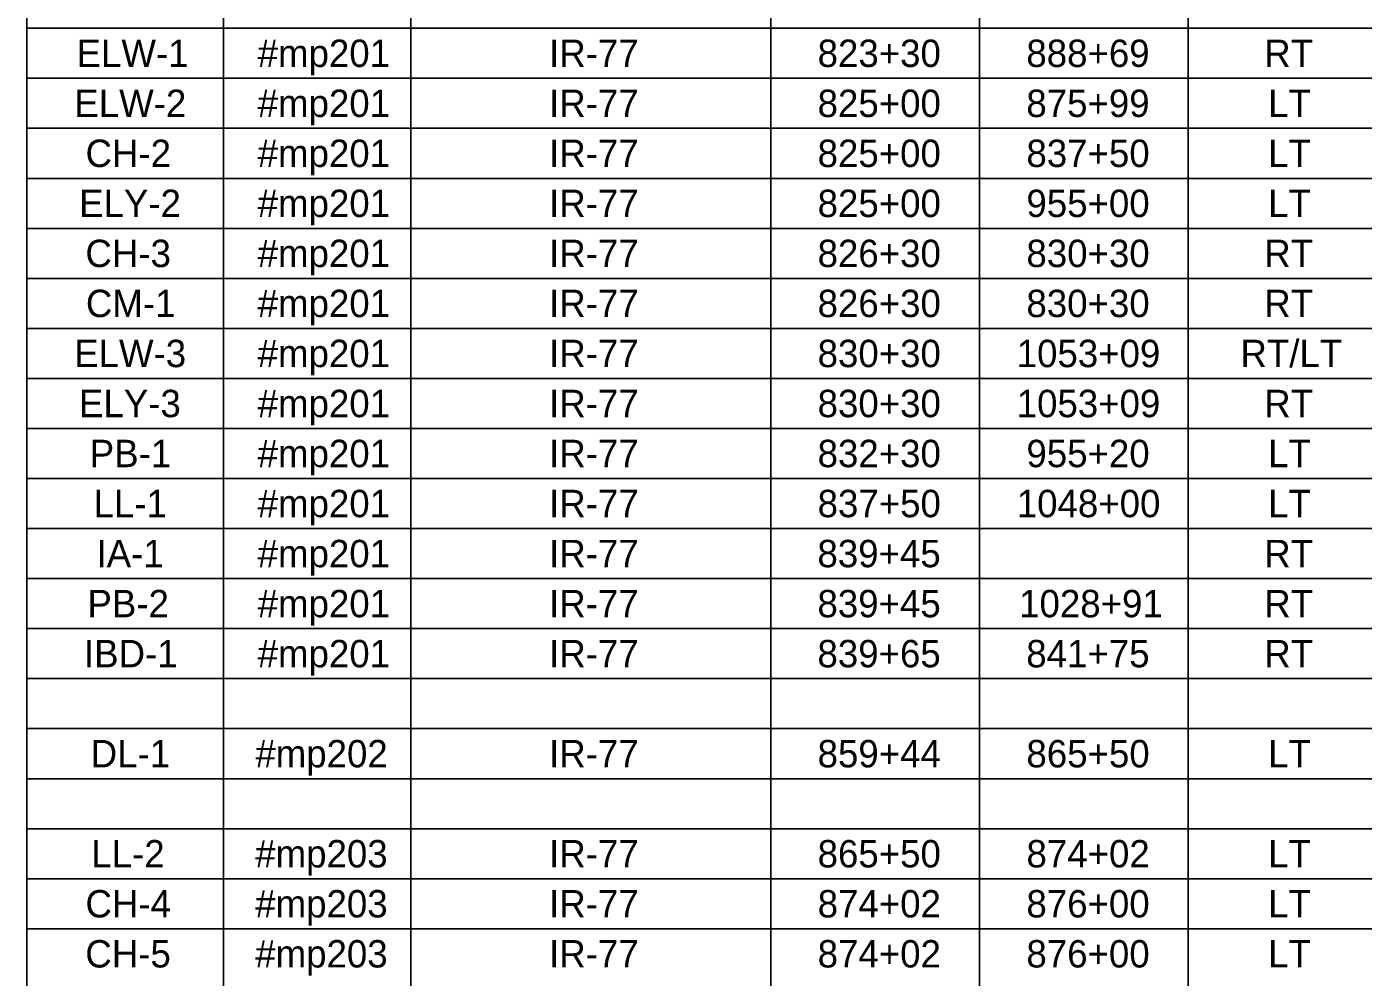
# Model space of a CAD drawing. Extents: x 91011267 to 91022583, y 37007614 to 37014266.
# Drawn here: x 91011277.4 to 91011644.4, y 37009419.7 to 37009680.8 of the extents above; entities that cross this region are included whole.
import ezdxf

# ---------------------------------------------------------------- set-up
doc = ezdxf.new("R2010")
doc.units = 0
doc.layers.add('SC_Scratch2', color=7, linetype='Continuous')
doc.layers.add('SH_Data', color=7, linetype='Continuous')

msp = doc.modelspace()

# ---------------------------------------------------------------- linework, layer by layer
at = {"layer": 'SC_Scratch2'}
msp.add_lwpolyline([(91011277.35, 37009944.63), (91012802.35, 37009944.63), (91012802.35, 37008894.63), (91011277.35, 37008894.63)], close=True, dxfattribs=at)
at = {"layer": 'SH_Data'}
for p, q in [((91011277.35, 37009762.76), (91011277.35, 37009652.86)), ((91011331.39, 37009762.76), (91011331.39, 37009652.86)), ((91011382.8, 37009762.76), (91011382.8, 37009652.86)), ((91011481.65, 37009762.76), (91011481.65, 37009652.86)), ((91011538.99, 37009762.76), (91011538.99, 37009652.86)), ((91011596.32, 37009762.76), (91011596.32, 37009652.86)), ((91011277.35, 37009680.33), (91011596.32, 37009680.33)), ((91011596.32, 37009680.33), (91011650.36, 37009680.33)), ((91011277.35, 37009666.59), (91011596.32, 37009666.59)), ((91011596.32, 37009666.59), (91011650.36, 37009666.59)), ((91011277.35, 37009652.86), (91011596.32, 37009652.86)), ((91011277.35, 37009652.86), (91011277.35, 37009639.12)), ((91011331.39, 37009652.86), (91011331.39, 37009639.12)), ((91011382.8, 37009652.86), (91011382.8, 37009639.12)), ((91011481.65, 37009652.86), (91011481.65, 37009639.12)), ((91011538.99, 37009652.86), (91011538.99, 37009639.12)), ((91011596.32, 37009652.86), (91011650.36, 37009652.86)), ((91011596.32, 37009652.86), (91011596.32, 37009639.12)), ((91011277.35, 37009639.12), (91011596.32, 37009639.12)), ((91011277.35, 37009639.12), (91011277.35, 37009611.64)), ((91011331.39, 37009639.12), (91011331.39, 37009611.64)), ((91011382.8, 37009639.12), (91011382.8, 37009611.64)), ((91011481.65, 37009639.12), (91011481.65, 37009611.64)), ((91011538.99, 37009639.12), (91011538.99, 37009611.64)), ((91011596.32, 37009639.12), (91011650.36, 37009639.12)), ((91011596.32, 37009639.12), (91011596.32, 37009611.64)), ((91011277.35, 37009625.38), (91011596.32, 37009625.38)), ((91011596.32, 37009625.38), (91011650.36, 37009625.38)), ((91011277.35, 37009611.64), (91011596.32, 37009611.64)), ((91011277.35, 37009611.64), (91011277.35, 37009597.9)), ((91011331.39, 37009611.64), (91011331.39, 37009597.9)), ((91011382.8, 37009611.64), (91011382.8, 37009597.9)), ((91011481.65, 37009611.64), (91011481.65, 37009597.9)), ((91011538.99, 37009611.64), (91011538.99, 37009597.9)), ((91011596.32, 37009611.64), (91011650.36, 37009611.64)), ((91011596.32, 37009611.64), (91011596.32, 37009597.9)), ((91011277.35, 37009597.9), (91011596.32, 37009597.9)), ((91011277.35, 37009597.9), (91011277.35, 37009584.17)), ((91011331.39, 37009597.9), (91011331.39, 37009584.17)), ((91011382.8, 37009597.9), (91011382.8, 37009584.17)), ((91011481.65, 37009597.9), (91011481.65, 37009584.17)), ((91011538.99, 37009597.9), (91011538.99, 37009584.17)), ((91011596.32, 37009597.9), (91011650.36, 37009597.9)), ((91011596.32, 37009597.9), (91011596.32, 37009584.17)), ((91011277.35, 37009584.17), (91011596.32, 37009584.17)), ((91011277.35, 37009584.17), (91011277.35, 37009570.43)), ((91011331.39, 37009584.17), (91011331.39, 37009570.43)), ((91011382.8, 37009584.17), (91011382.8, 37009570.43)), ((91011481.65, 37009584.17), (91011481.65, 37009570.43)), ((91011538.99, 37009584.17), (91011538.99, 37009570.43)), ((91011596.32, 37009584.17), (91011650.36, 37009584.17)), ((91011596.32, 37009584.17), (91011596.32, 37009570.43)), ((91011277.35, 37009570.43), (91011596.32, 37009570.43)), ((91011277.35, 37009570.43), (91011277.35, 37009364.35)), ((91011331.39, 37009570.43), (91011331.39, 37009364.35)), ((91011382.8, 37009570.43), (91011382.8, 37009364.35)), ((91011481.65, 37009570.43), (91011481.65, 37009364.35)), ((91011538.99, 37009570.43), (91011538.99, 37009364.35)), ((91011596.32, 37009570.43), (91011650.36, 37009570.43)), ((91011596.32, 37009570.43), (91011596.32, 37009364.35)), ((91011277.35, 37009556.69), (91011596.32, 37009556.69)), ((91011596.32, 37009556.69), (91011650.36, 37009556.69)), ((91011277.35, 37009542.95), (91011596.32, 37009542.95)), ((91011596.32, 37009542.95), (91011650.36, 37009542.95)), ((91011277.35, 37009529.21), (91011596.32, 37009529.21)), ((91011596.32, 37009529.21), (91011650.36, 37009529.21)), ((91011277.35, 37009515.47), (91011596.32, 37009515.47)), ((91011596.32, 37009515.47), (91011650.36, 37009515.47)), ((91011277.35, 37009501.74), (91011596.32, 37009501.74)), ((91011596.32, 37009501.74), (91011650.36, 37009501.74)), ((91011277.35, 37009488), (91011596.32, 37009488)), ((91011596.32, 37009488), (91011650.36, 37009488)), ((91011277.35, 37009474.26), (91011596.32, 37009474.26)), ((91011596.32, 37009474.26), (91011650.36, 37009474.26)), ((91011277.35, 37009460.52), (91011596.32, 37009460.52)), ((91011596.32, 37009460.52), (91011650.36, 37009460.52)), ((91011277.35, 37009446.78), (91011596.32, 37009446.78)), ((91011596.32, 37009446.78), (91011650.36, 37009446.78)), ((91011277.35, 37009433.04), (91011596.32, 37009433.04)), ((91011596.32, 37009433.04), (91011650.36, 37009433.04))]:
    msp.add_line(p, q, dxfattribs=at)

# ---------------------------------------------------------------- texts
for s, p in [('ELW-1', (91011291.04, 37009669.7)), ('#mp201', (91011340.76, 37009669.7)), ('IR-77', (91011420.79, 37009669.7)), ('823+30', (91011494.52, 37009669.7)), ('888+69', (91011551.84, 37009669.7)), ('RT', (91011617.17, 37009669.7)), ('ELW-2', (91011290.42, 37009655.96)), ('#mp201', (91011340.76, 37009655.96)), ('IR-77', (91011420.79, 37009655.96)), ('825+00', (91011494.52, 37009655.96)), ('875+99', (91011551.84, 37009655.96)), ('LT', (91011618.23, 37009655.96)), ('CH-2', (91011293.5, 37009642.23)), ('#mp201', (91011340.76, 37009642.23)), ('IR-77', (91011420.79, 37009642.23)), ('825+00', (91011494.52, 37009642.23)), ('837+50', (91011551.86, 37009642.23)), ('LT', (91011618.23, 37009642.23)), ('ELY-2', (91011291.73, 37009628.49)), ('#mp201', (91011340.76, 37009628.49)), ('IR-77', (91011420.79, 37009628.49)), ('825+00', (91011494.52, 37009628.49)), ('955+00', (91011551.86, 37009628.49)), ('LT', (91011618.23, 37009628.49)), ('CH-3', (91011293.47, 37009614.75)), ('#mp201', (91011340.76, 37009614.75)), ('IR-77', (91011420.79, 37009614.75)), ('826+30', (91011494.52, 37009614.75)), ('830+30', (91011551.86, 37009614.75)), ('RT', (91011617.17, 37009614.75)), ('CM-1', (91011293.6, 37009601.01)), ('#mp201', (91011340.76, 37009601.01)), ('IR-77', (91011420.79, 37009601.01)), ('826+30', (91011494.52, 37009601.01)), ('830+30', (91011551.86, 37009601.01)), ('RT', (91011617.17, 37009601.01)), ('ELW-3', (91011290.38, 37009587.27)), ('#mp201', (91011340.76, 37009587.27)), ('IR-77', (91011420.79, 37009587.27)), ('830+30', (91011494.52, 37009587.27)), ('1053+09', (91011549.19, 37009587.27)), ('RT/LT', (91011610.64, 37009587.27)), ('ELY-3', (91011291.7, 37009573.53)), ('#mp201', (91011340.76, 37009573.53)), ('IR-77', (91011420.79, 37009573.53)), ('830+30', (91011494.52, 37009573.53)), ('1053+09', (91011549.19, 37009573.53)), ('RT', (91011617.17, 37009573.53)), ('PB-1', (91011294.65, 37009559.8)), ('#mp201', (91011340.76, 37009559.8)), ('IR-77', (91011420.79, 37009559.8)), ('832+30', (91011494.52, 37009559.8)), ('955+20', (91011551.86, 37009559.8)), ('LT', (91011618.23, 37009559.8)), ('LL-1', (91011295.71, 37009546.06)), ('#mp201', (91011340.76, 37009546.06)), ('IR-77', (91011420.79, 37009546.06)), ('837+50', (91011494.52, 37009546.06)), ('1048+00', (91011549.21, 37009546.06)), ('LT', (91011618.23, 37009546.06)), ('IA-1', (91011296.51, 37009532.32)), ('#mp201', (91011340.76, 37009532.32)), ('IR-77', (91011420.79, 37009532.32)), ('839+45', (91011494.48, 37009532.32)), ('RT', (91011617.17, 37009532.32)), ('PB-2', (91011294.03, 37009518.58)), ('#mp201', (91011340.76, 37009518.58)), ('IR-77', (91011420.79, 37009518.58)), ('839+45', (91011494.48, 37009518.58)), ('1028+91', (91011549.86, 37009518.58)), ('RT', (91011617.17, 37009518.58)), ('IBD-1', (91011293.07, 37009504.84)), ('#mp201', (91011340.76, 37009504.84)), ('IR-77', (91011420.79, 37009504.84)), ('839+65', (91011494.48, 37009504.84)), ('841+75', (91011551.82, 37009504.84)), ('RT', (91011617.17, 37009504.84)), ('DL-1', (91011294.92, 37009477.37)), ('#mp202', (91011340.13, 37009477.37)), ('IR-77', (91011420.79, 37009477.37)), ('859+44', (91011494.52, 37009477.37)), ('865+50', (91011551.86, 37009477.37)), ('LT', (91011618.23, 37009477.37)), ('LL-2', (91011295.09, 37009449.89)), ('#mp203', (91011340.1, 37009449.89)), ('IR-77', (91011420.79, 37009449.89)), ('865+50', (91011494.52, 37009449.89)), ('874+02', (91011551.88, 37009449.89)), ('LT', (91011618.23, 37009449.89)), ('CH-4', (91011293.48, 37009436.15)), ('#mp203', (91011340.1, 37009436.15)), ('IR-77', (91011420.79, 37009436.15)), ('874+02', (91011494.54, 37009436.15)), ('876+00', (91011551.86, 37009436.15)), ('LT', (91011618.23, 37009436.15)), ('CH-5', (91011293.44, 37009422.41)), ('#mp203', (91011340.1, 37009422.41)), ('IR-77', (91011420.79, 37009422.41)), ('874+02', (91011494.54, 37009422.41)), ('876+00', (91011551.86, 37009422.41)), ('LT', (91011618.23, 37009422.41))]:
    msp.add_text(s, height=7.523, dxfattribs=at).set_placement(p)

doc.saveas('drawing.dxf')
